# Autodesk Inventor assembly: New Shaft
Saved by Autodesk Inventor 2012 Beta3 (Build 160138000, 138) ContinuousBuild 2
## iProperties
Created: 2011-01
Part Number: New Shaft
Document SubType Name: Assembly
Designer: Beta-8540w
ClientObjectVersion: 1
Author: Beta-8540w
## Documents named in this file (2)
- C:\Inventor 2012 Essentials\Assemblies\Chapter 8\Design Accelerators\Shaft c8-07.iam
- C:\Inventor 2012 Essentials\Assemblies\Chapter 8\Design Accelerators\Shaft c8-05.ipt
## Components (1 placed, 1 different names)
1. New Shaft:1
